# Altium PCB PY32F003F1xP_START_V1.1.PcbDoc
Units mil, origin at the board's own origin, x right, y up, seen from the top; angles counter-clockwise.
Board outline 2126.87 x 1182.75 mil, 2 copper layers (Top Layer, Bottom Layer); 29 components, 28 nets, 127 pads, 22 vias.
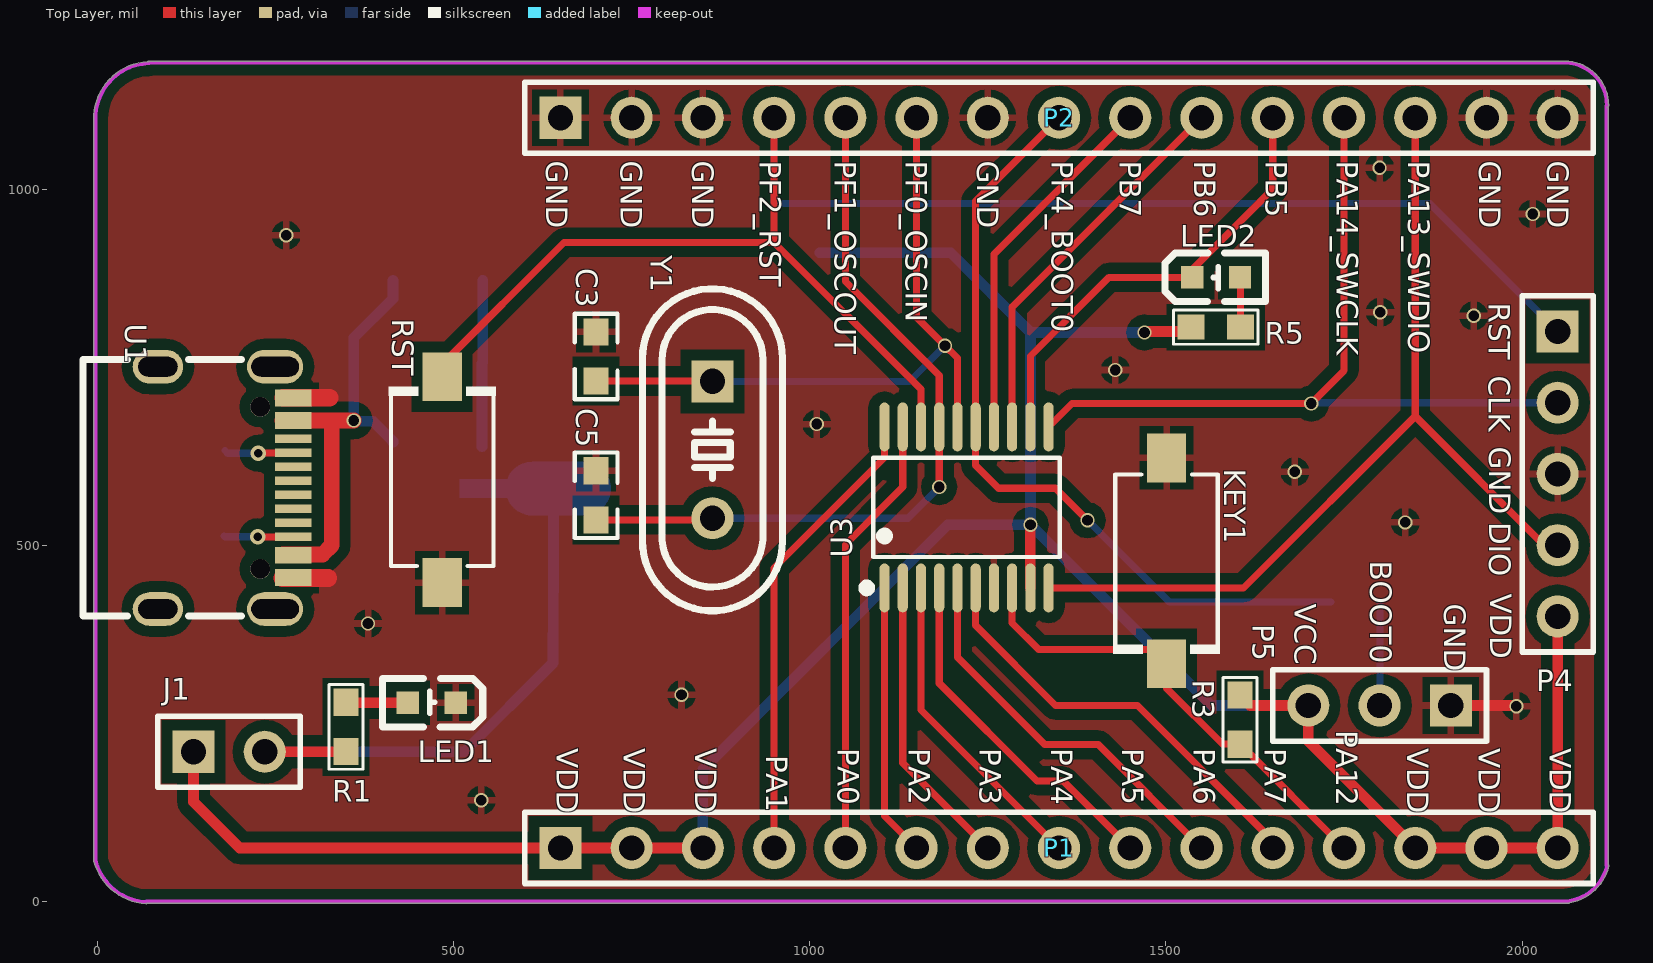
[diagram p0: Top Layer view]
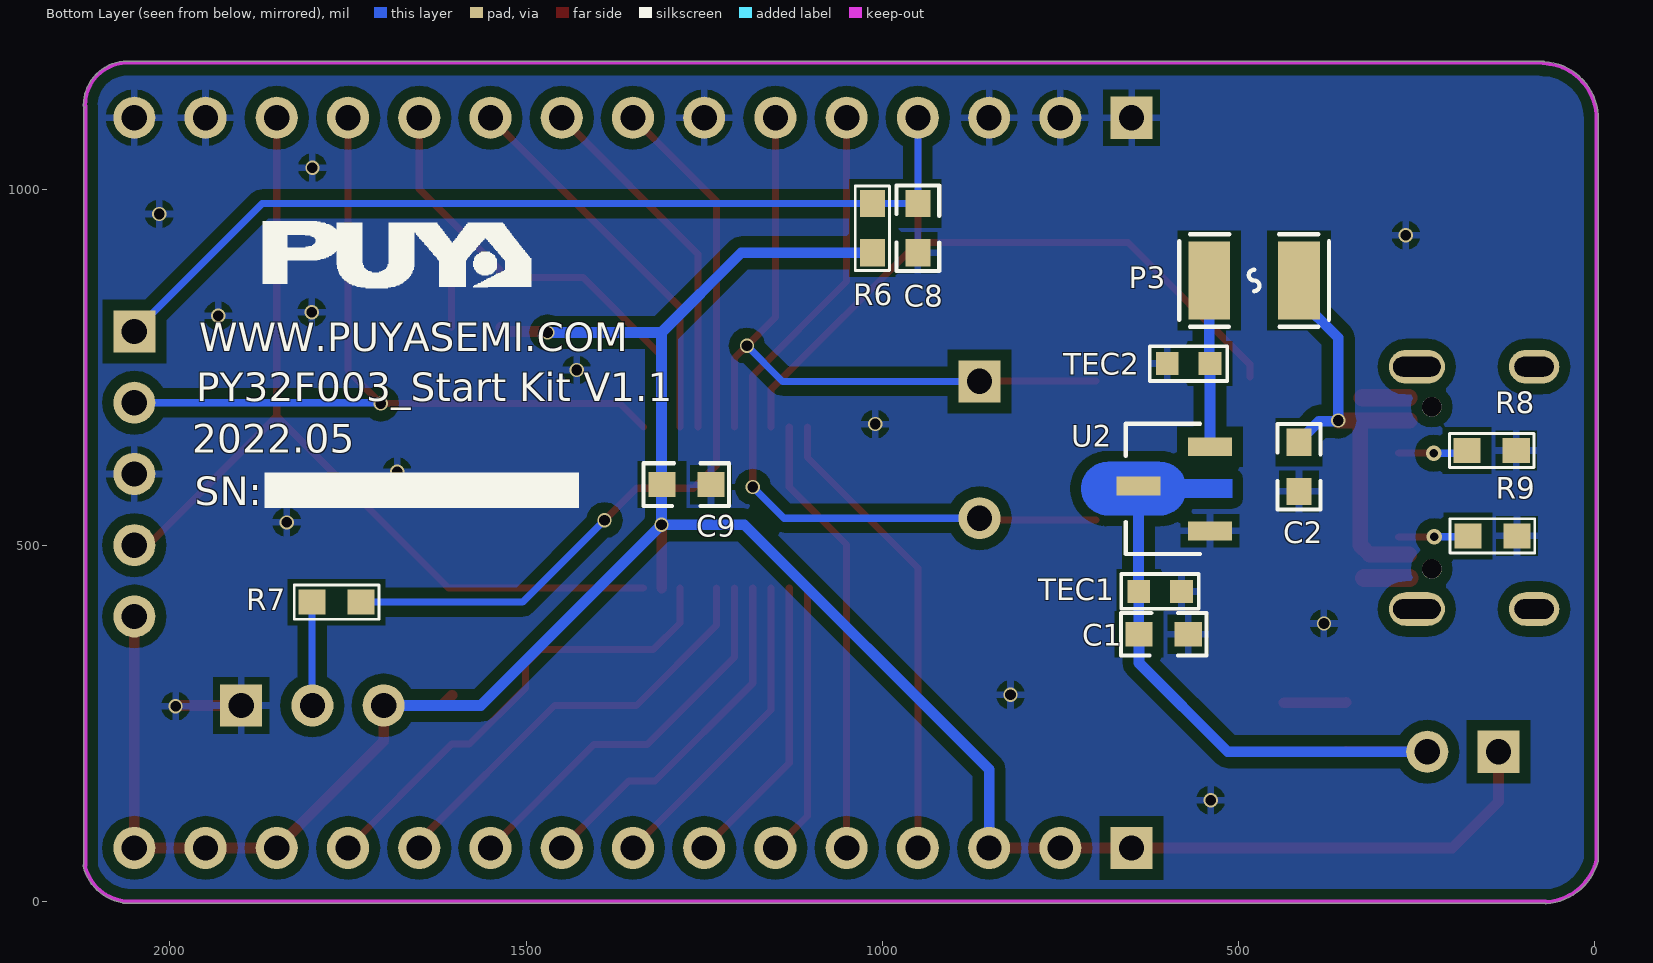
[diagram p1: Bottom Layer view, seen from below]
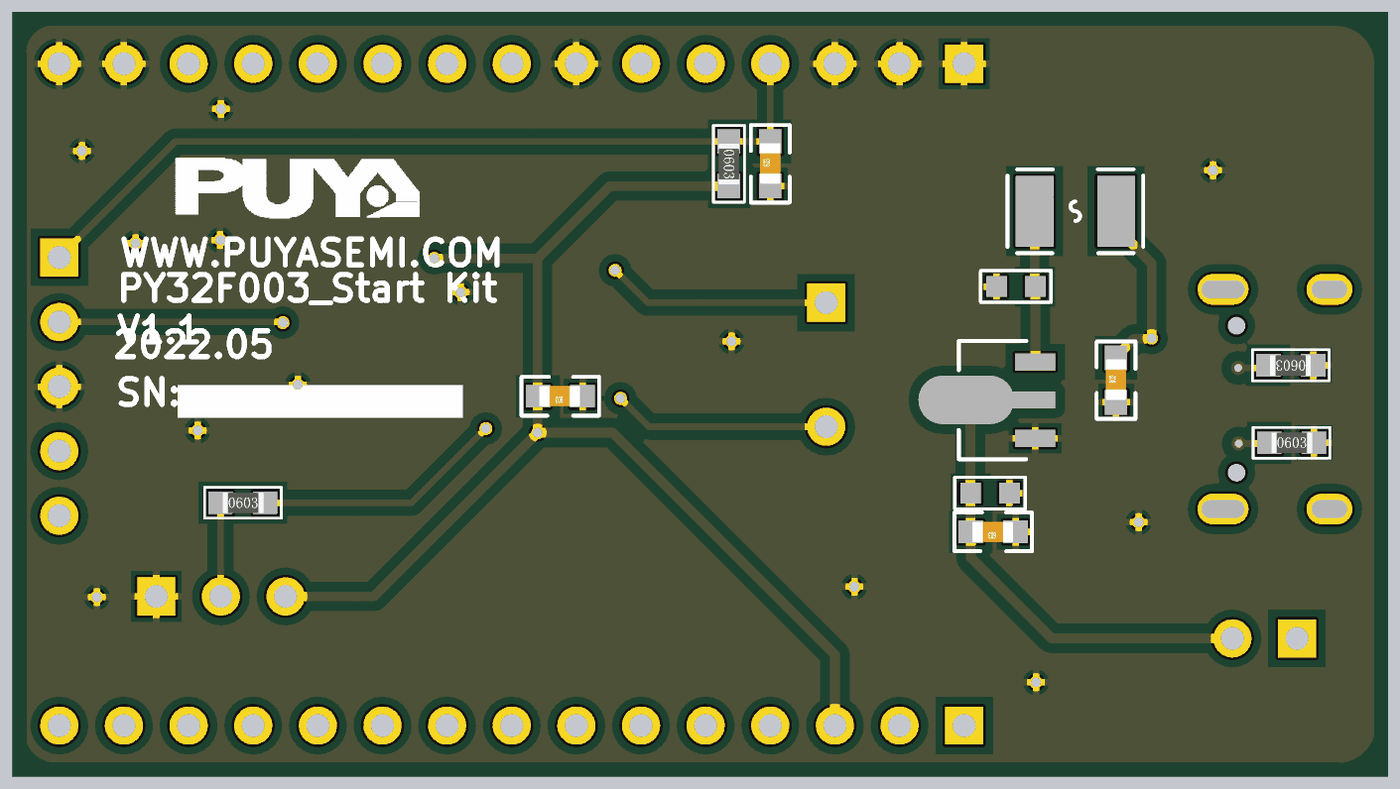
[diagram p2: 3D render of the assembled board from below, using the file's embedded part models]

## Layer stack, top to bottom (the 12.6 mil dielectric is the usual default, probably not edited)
Top Layer: signal copper 1.4
Dielectric: dielectric 12.6, FR-4, Dk 4.8
Bottom Layer: signal copper 1.4

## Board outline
68.32,-3.24 cw(c72.79,76.93) -4.93,56.79 cw(c-2.5,57.42) -5.02,57.42 -5.02,1096.79 cw(c-2.51,1097) -5.02,1096.93 cw(c74.74,1099.04) 70.88,1178.73 cw(c72.7,1177) 72.7,1179.52 2060,1179.52 cw(c2060,1177) 2060.02,1179.52 cw(c2059.5,1117.5) 2121.52,1117.5 cw(c2059.5,1117.5) 2121.51,1116.98 cw(c2119,1117) 2118.86,1114.49 cw(c2118.5,1112) 2121.01,1112 2121.01,51.66 cw(c2119.33,49.8) 2121.84,49.8 cw(c2119.33,49.8) 2121.77,49.2 cw(c2055.5,65.5) 2066.74,-1.81 cw(c2065,0) 2065,-2.51 2061.11,-2.51 cw(c2055.5,65.5) 2049.89,-2.51 70.23,-2.51 cw(c68.46,-0.72)

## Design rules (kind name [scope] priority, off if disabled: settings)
Clearance poly [InPolygon] p1: gap=15
Clearance [All] p2: gap=6
ComponentClearance [All] p1: gap=0 collisioncheckmode=3 verticalgap=0 showdistances=FALSE
HoleToHoleClearance [All] p1: gap=3 allowstackedmicrovias=TRUE
MinimumSolderMaskSliver [All] p1: minsoldermaskwidth=0
NetAntennae [All] p1: netantennaetolerance=6
PolygonConnect [All] p1: connectstyle=Relief reliefconductorwidth=10 reliefentries=4 polygonreliefangle="90 Angle"
RoutingVias [All] p1: holewidth=28 width=50 viastyle="Through Hole" minholewidth=28 minwidth=50 maxholewidth=28 maxwidth=50
SilkToSilkClearance [All] p1: silktosilkclearance=0
SilkscreenOverComponentPads SilkToSolderMaskClearance [IsPad] p1: minsilkscreentomaskgap=0
SolderMaskExpansion [All] p1: expansion=4
Width [All] p1: maxlimit=30 minlimit=10 preferedwidth=10
22 further rules are at their usual default settings.

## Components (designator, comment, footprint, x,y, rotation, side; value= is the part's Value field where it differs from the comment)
C1 "0.1uF/50V" 0603C 605,375 r0 bottom
C2 "0.1uF/50V" 0603C 415,610 r90 bottom
C3 "22pF" 0603C 700,765 r270 top
C5 "22pF" 0603C 700,570 r90 top
C8 "0.1uF/50V" 0603C 950,945 r90 bottom
C9 "0.1uF/50V" 0603C 1275,585 r0 bottom
J1 "JUMP" HDR1X2 135,210 r0 top
KEY1 "1TS002B-2600-5001" SW 1500,525 r270 top (schematic designator SW1)
LED1 "RED" 0603_LED 455,280 r180 top
LED2 "GREEN" 0603_LED 1585,875 r0 top
P1 "Header 15" HDR1X15 650,75 r0 top
P2 "Header 15" HDR1X15 650,1100 r0 top
P3 "SMD1210P005TF" SDM1210P005TF 475,850 r0 bottom
P4 "Debug" HDR1X5 2050,800 r270 top
P5 "Header 3" HDR1X3 1900,275 r180 top
R1 "470Ω" 0603R 350,245 r90 top
R3 "1.5K" 0603R 1605,255 r90 top
R5 "680Ω" 0603R 1570,805 r0 top
R6 "10K" 0603R 1015,945 r270 bottom
R7 "10K" 0603R 1766,419 r180 bottom
R8 "5.1k" 0603R 144.5,634 r0 bottom
R9 "5.1K" 0603R 143.5,512 r180 bottom
RST "1TS002B-2600-5001" SW 485,545 r90 top (schematic designator SW3)
TEC1 "10uF" 0603 610,435 r0 bottom
TEC2 "10uF" 0603 570,755 r180 bottom
U1 "KH-TYPE-C-16P" USB-C-SMD_KH-TYPE-C-16P 135,574 r270 top
U2 "LM1117-3.3" LM1117-3.3 540,520 r180 bottom
U3 "PY32F003" TSSOP20 1105,440 r0 top
Y1 "24M" 25MHZ_2 860,600 r270 top

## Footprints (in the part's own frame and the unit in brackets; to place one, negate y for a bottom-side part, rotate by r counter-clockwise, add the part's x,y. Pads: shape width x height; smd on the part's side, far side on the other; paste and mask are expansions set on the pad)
25MHZ_2 [mm]
  rect 1.5x1.5 hole 0.9: 1(-3.302,0.087)
  round 1.5 hole 0.9: 2(1.578,0.087)
  silkscreen extent -6.6,-2.41 4.88,2.59
0603 [mil]
  rect 32x32 smd: 1(30,0) 2(-30,0)
  silkscreen extent -54,-25 55,24
0603_LED [mil]
  rect 31.5x31.5 smd: 1(19,1) 2(-48,1)
  silkscreen extent -86,-33 55,35
0603C [mil]
  rect 38x35 smd: 1(-34.5,0) 2(34.5,0)
  silkscreen extent -60,-30 60,30, body extent -31,-16 32,16, height 12
0603R [mil]
  rect 38x35 smd: 1(-34.5,1) 2(34.5,1)
  silkscreen extent -59,-23 59,25, body extent -31,-15 32,17, height 18
HDR1X2 [mm] "Connector; Header; 2 Position"
  rect 1.5x1.5 hole 0.9: 1(0,0)
  round 1.5 hole 0.9: 2(2.54,0)
  silkscreen extent -1.27,-1.27 3.81,1.27
HDR1X3 [mm] "Connector; Header; 3 Position"
  rect 1.5x1.5 hole 0.9: 1(0,0)
  round 1.5 hole 0.9: 2(2.54,0) 3(5.08,0)
  silkscreen extent -1.27,-1.27 6.35,1.27
HDR1X5 [mm] "Connector; Header; 5 Position"
  rect 1.5x1.5 hole 0.9: 1(0,0)
  round 1.5 hole 0.9: 2(2.54,0) 3(5.08,0) 4(7.62,0) 5(10.16,0)
  silkscreen extent -1.27,-1.27 11.43,1.27
HDR1X15 [mm]
  rect 1.5x1.5 hole 0.9: 1(0,0)
  round 1.5 hole 0.9: 2(2.54,0) 3(5.08,0) 4(7.62,0) 5(10.16,0) 6(12.7,0) 7(15.24,0) 8(17.78,0) 9(20.32,0) 10(22.86,0) 11(25.4,0) 12(27.94,0) 13(30.48,0) 14(33.02,0) 15(35.56,0)
  silkscreen extent -1.27,-1.27 36.83,1.27
LM1117-3.3 [mm]
  rect 1.575x0.672 smd: 1(0,0) 2(-2.55,1.598) 3(0,3)
  Top Layer region: -3.64,2.459 -1.785,2.459 -1.741,2.458 -1.696,2.455 -1.652,2.449 -1.608,2.442 -1.565,2.433 -1.522,2.421 -1.479,2.408 -1.437,2.393 -1.396,2.375 -1.356,2.356 -1.317,2.335 -1.279,2.312 -1.241,2.288 -1.206,2.261 -1.171,2.233 -1.138,2.204 -1.106,2.173 -1.075,2.14 -1.047,2.106 -1.019,2.071 -0.994,2.034 -0.97,1.996 -0.948,1.958 -0.928,1.918 -0.91,1.839 0.788,1.839 0.788,1.179 -0.91,1.179 -0.928,1.099 -0.948,1.06 -0.97,1.021 -0.994,0.983 -1.019,0.947 -1.047,0.911 -1.075,0.877 -1.106,0.845 -1.138,0.814 -1.171,0.784 -1.206,0.756 -1.241,0.73 -1.279,0.705 -1.317,0.682 -1.356,0.661 -1.396,0.642 -1.437,0.625 -1.479,0.609 -1.522,0.596 -1.565,0.585 -1.608,0.575 -1.652,0.568 -1.696,0.563 -1.741,0.56 -1.785,0.559 -3.64,0.559 -3.684,0.56 -3.728,0.563 -3.773,0.568 -3.817,0.575 -3.86,0.585 -3.903,0.596 -3.946,0.609 -3.988,0.625 -4.029,0.642 -4.069,0.661 -4.108,0.682 -4.146,0.705 -4.183,0.73 -4.219,0.756 -4.254,0.784 -4.287,0.814 -4.319,0.845 -4.349,0.877 -4.378,0.911 -4.405,0.947 -4.431,0.983 -4.455,1.021 -4.477,1.06 -4.497,1.099 -4.515,1.14 -4.531,1.181 -4.546,1.224 -4.558,1.266 -4.568,1.31 -4.577,1.353 -4.583,1.398 -4.587,1.442 -4.589,1.486 -4.589,1.531 -4.587,1.575 -4.583,1.62 -4.577,1.664 -4.568,1.708 -4.558,1.751 -4.546,1.794 -4.531,1.836 -4.515,1.877 -4.497,1.918 -4.477,1.958 -4.455,1.996 -4.431,2.034 -4.405,2.071 -4.378,2.106 -4.349,2.14 -4.319,2.173 -4.287,2.204 -4.254,2.233 -4.219,2.261 -4.183,2.288 -4.146,2.312 -4.108,2.335 -4.069,2.356 -4.029,2.375 -3.988,2.393 -3.946,2.408 -3.903,2.421 -3.86,2.433 -3.817,2.442 -3.773,2.449 -3.728,2.455 -3.684,2.458
  silkscreen extent -3.01,-0.83 -0.35,3.83
SDM1210P005TF [mm]
  rect 1.485x2.781 smd: 1(-1.524,-0.549) 2(1.676,-0.549)
  silkscreen extent -2.59,-2.2 2.74,1.1
SW [mm]
  rect 1.74x1.4 smd: 1(-2.476,0.024) 2(4.864,0.024)
  silkscreen extent -1.88,-1.88 4.5,1.93
TSSOP20 [mm]
  oval 0.364x1.742 smd: 1(0,0) 2(0.65,0) 3(1.3,0) 4(1.95,0) 5(2.6,0) 6(3.25,0) 7(3.9,0) 8(4.55,0) 9(5.2,0) 10(5.85,0) 11(5.85,5.742) 12(5.2,5.742) 13(4.55,5.742) 14(3.9,5.742) 15(3.25,5.742) 16(2.6,5.742) 17(1.95,5.742) 18(1.3,5.742) 19(0.65,5.742) 20(0,5.742)
  silkscreen extent -0.78,-0.15 6.25,4.64
USB-C-SMD_KH-TYPE-C-16P [mm] "https://item.szlcsc.com/747093.html"
  oval 1.2x2 hole 0.7 slot 1.7 at 90 deg: 1(-4.484,2.908) 2(4.156,2.908)
  oval 1.2x1.8 hole 0.7 slot 1.4 at 90 deg: 3(-4.484,-1.272) 4(4.156,-1.272)
  rect 0.3x1.3 smd: A1(-3.514,3.558) A4(-2.714,3.558) A5(-1.414,3.558) A6(-0.414,3.558) A7(0.086,3.558) A8(1.086,3.558) A9(2.386,3.558) A12(3.186,3.558) B1(2.886,3.558) B4(2.086,3.558) B5(1.586,3.558) B6(0.586,3.558) B7(-0.914,3.558) B8(-1.914,3.558) B9(-2.414,3.558) B12(-3.214,3.558)
  round 0.7 hole 0.7 unplated: ""(-3.054,2.378) ""(2.726,2.378)
  silkscreen extent -4.74,-3.94 4.41,1.72

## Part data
C1 C3 C5: library part Cap, "Capacitor"
C2 C8 C9: library part CAP, "Capacitor"
LED1 LED2: library part PDI-E803_Dup1
P1 P2: "Header, 15-Pin"
P4: library part CON5
P5: "Header, 3-Pin"
R1 R3 R5 R6 R7: library part Res, "Resistor"
R8 R9: library part Res_1, "Resistor"
TEC1 TEC2: library part 贴片钽电容
U3: library part Component_1
Y1: library part CRYSTAL, "Crystal"

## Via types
v1: diameter 20, hole 15, Top Layer to Bottom Layer, 20 vias
v2: diameter 22, hole 12, Top Layer to Bottom Layer, tented both sides, 2 vias

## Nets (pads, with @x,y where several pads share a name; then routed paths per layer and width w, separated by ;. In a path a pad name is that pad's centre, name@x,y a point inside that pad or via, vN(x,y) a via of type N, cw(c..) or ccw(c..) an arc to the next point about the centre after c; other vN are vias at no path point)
Boot0: P2.8 R7.2 U3.15 | length 1114.5
  Top Layer w10: P2.8 1232.95,982.95 U3.15 1232.95,612.05 1265,580 1345,580 v1(1390,535)
  Bottom Layer w10: v1(1390,535) 1505,420 R7.2
GND: C1.1 C2.1 C3.1 C5.2 C8.1 C9.1 KEY1.1 LED1.2 P2.1 P2.2 P2.3 P2.7 P2.14 P2.15 P4.3 P5.1 R8.1 R9.2 RST.1 TEC1.2 TEC2.2 U1.A1 U1.A12 U1.B1 U1.B12 U2.1 U3.7 | length 221.4
  Top Layer w15: P5.1 1991,275 v1(1992,274)
  Top Layer w25: U1.A12@260,454 324,454 ; U1.A1@261,707 326,707
  other v1: 539,142 820,290 380,390 1836,532 1681,603 1010,670 1429,746 1932,822 1801,827 265,935 2015,965 1800,1030
MCU_RST: C8.2 P2.4 P4.1 R6.1 RST.2 U3.18 | length 2368.5
  Top Layer w10: RST.2 484.04,754.04 655,925 950,925 ; P2.4 950,925 ; U3.18 1156.18,718.82 950,925
  Bottom Layer w10: P2.4 C8.2 R6.1 1870.5,979.5 P4.1
MCU_VDD: C9.2 J1.1 P1.1 P1.2 P1.3 P1.13 P1.14 P1.15 P4.5 P5.3 R3.2 R5.1 R6.2 U3.9 | length 3839.8
  Top Layer w15: J1.1 135,140 200,75 P1.1 P1.2 P1.3 ; U3.9 v1@1309.72,530 ; v1(1469.96,798.59) 1471.37,800 1529.5,800 R5.1 ; R3.2 1618.5,275 P5.3 1700,225 P1.13 P1.14 P1.15 P4.5
  Bottom Layer w15: P1.3 850,185 1193.59,528.59 v1(1309.96,528.59) ; R6.2 1198.13,910.5 1310.04,798.59 ; C9.2 1310.04,585.54 1310.04,798.59 ; C9.2 1310,584.54 v1(1309.96,528.59) v1(1309.96,528.59) ; v1(1469.96,798.59) 1310.04,798.59 ; P5.3 1563.54,275 v1(1309.96,528.59)
NetC1_2: C1.2 J1.2 R1.1 TEC1.1 U2.2 | length 819
  Top Layer w15: J1.2 348.5,210 R1.1
  Bottom Layer w15: J1.2 515,210 639.5,334.5 C1.2 640,375.5 TEC1.1 640.38,435.38 U2.2
NetLED1_1: LED1.1 R1.2 | length 87.2
  Top Layer w15: R1.2 349.5,279 LED1.1
NetLED2_1: LED2.1 R5.2 | length 69.5
  Top Layer w10: R5.2 LED2.1@1604.5,875.5
NetP3_2: P3.2 TEC2.1 U2.3 | length 233.9
  Bottom Layer w15: U2.3 TEC2.1 540.98,755.98 P3.2
NetP5_2: P5.2 R7.1 | length 145.2
  Bottom Layer w10: P5.2 1800.5,275.5 R7.1
NetR8_2: R8.2 U1.A5 | length 98
  Top Layer w10: v2(226,629) 226.67,629.67 U1.A5
  Bottom Layer w10: R8.2 183,629 v2(226,629)
NetR9_1: R9.1 U1.B5 | length 98
  Top Layer w10: v2@225,512 225.44,511.56 U1.B5
  Bottom Layer w10: R9.1 179.22,511.78 v2(225.22,511.78)
OSCIN: C3.2 P2.6 U3.16 Y1.1 | length 968.6
  Top Layer w10: C3.2 862.91,730.5 Y1.1 ; P2.6 1150,820 v1(1190,780) 1207.36,762.64 U3.16
  Bottom Layer w10: Y1.1 1139.99,729.99 v1(1190,780)
OSCOUT: C5.1 P2.5 U3.17 Y1.2 | length 1073.7
  Top Layer w10: C5.1 861.06,535.5 Y1.2 ; P2.5 1050,870 1181.77,738.23 U3.17 v1(1181.77,581.77)
  Bottom Layer w10: Y1.2 1137.86,537.86 v1(1181.77,581.77)
PA0: P1.5 U3.19 | length 624.4
  Top Layer w10: P1.5 1050,501 1130.59,581.59 U3.19
PA1: P1.4 U3.20 | length 655.3
  Top Layer w10: P1.4 950,468 1105,623 U3.20
PA2: P1.6 U3.1 | length 383.6
  Top Layer w10: U3.1 1105,120 P1.6
PA3: P1.7 U3.2 | length 414.5
  Top Layer w10: U3.2 1130.59,194.41 P1.7
PA4: P1.8 U3.3 | length 445.3
  Top Layer w10: U3.3 1156.18,268.82 P1.8
PA5: P1.9 U3.4 | length 497.8
  Top Layer w10: U3.4 1181.77,306.23 1319,169 1356,169 P1.9
PA6: P1.10 U3.5 | length 550.9
  Top Layer w10: U3.5 1207.36,342.64 1330,220 1405,220 P1.10
PA7: P1.11 U3.6 | length 605.1
  Top Layer w10: U3.6 1232.95,387.05 1345,275 1460,275 1650,85 P1.11
PA12: KEY1.2 P1.12 R3.1 U3.8 | length 666
  Top Layer w10: U3.8 1284.13,390.87 1321.5,353.5 1480.96,353.5 KEY1.2 1500.96,299.04 1579.25,220.75 1604.25,220.75 P1.12
PB5: LED2.2 P2.11 U3.12 | length 643.4
  Top Layer w10: U3.12 1309.72,765.72 1420,876 LED2.2 1537,887 1650,1000 P2.11
PB6: P2.10 U3.13 | length 544.1
  Top Layer w10: U3.13 1284.13,834.13 P2.10
PB7: P2.9 U3.14 | length 513.2
  Top Layer w10: U3.14 1258.54,908.54 P2.9
SWCLK: P2.12 P4.2 U3.11 | length 1150.4
  Top Layer w10: U3.11 1368.25,699 v1(1704,699) ; v1@1706,699 v1(1704,699) ; P2.12 1750,745 v1(1704,699)
  Bottom Layer w10: v1@1704,700 P4.2
SWDIO: P2.13 P4.4 U3.10 | length 1308.5
  Top Layer w10: U3.10 1609,440 1850,681 ; P2.13 1850,681 ; P4.4 2031,500 1850,681
Type_C: C2.2 P3.1 U1.A4 U1.A9 U1.B4 U1.B9 | length 637.7
  Top Layer w22: U1.A4@259.66,675 329,675 ; U1.B4@260,487 316.11,487 329,499.89 329,675 ; v1(360,675) 329,675
  Bottom Layer w15: C2.2 415,646 386.96,674.04 360.96,674.04 v1(360,675) 360,791.09 415,846.09 P3.1
pads on no net: U1. U1.1 U1.2 U1.3 U1.4 U1.A6 U1.A7 U1.A8 U1.B6 U1.B7 U1.B8

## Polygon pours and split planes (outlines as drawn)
GND on Bottom Layer "Top-GND" (solid, remove dead copper, pour order 13): -4,1177 2118,1177 2118,1 -1,1
GND on Top Layer "Top-GND" (solid, remove dead copper, pour order 15): -1,1 2118,1 2118,1177 -3,1177

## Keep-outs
Keep-Out Layer:
  lines w5: -2.51,1097 cw(c74.74,1099.04) 72.7,1176.28 ; -2.5,1098 -2.5,57.42 ccw(c72.79,76.93) 68.46,-0.72 ; 68.5,0 2065,0 ; 72.7,1177 262.5,1177 2059.5,1177 ; 2050,0 ccw(c2055.5,65.5) 2119.33,49.8 ; 2060,1177 cw(c2059.5,1117.5) 2119,1117 ; 2118.5,50 2118.5,1117

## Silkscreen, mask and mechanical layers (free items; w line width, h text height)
Top Overlay:
  text "GND" at 630,1040 h30 r270
  text "GND" at 735,1040 h30 r270
  text "GND" at 835,1040 h30 r270
  text "PF2_RST" at 930,1040 h30 r270
  text "PF1_OSCOUT" at 1035,1040 h30 r270
  text "PF0_OSCIN" at 1135,1040 h30 r270
  text "GND" at 1235,1040 h30 r270
  text "PF4_BOOT0" at 1340,1040 h30 r270
  text "PB7" at 1435,1040 h30 r270
  text "PB6" at 1540,1040 h30 r270
  text "PB5" at 1640,1040 h30 r270
  text "PA14_SWCLK" at 1740,1040 h30 r270
  text "PA13_SWDIO" at 1840,1040 h30 r270
  text "GND" at 1940,1040 h30 r270
  text "GND" at 2035,1040 h30 r270
  text "RST" at 1953,840 h30 r270
  text "CLK" at 1953,738 h30 r270
  text "GND" at 1954,638 h30 r270
  text "DIO" at 1954,532 h30 r270
  text "BOOT0" at 1787,478.02 h30 r270
  text "VDD" at 1955,432 h30 r270
  text "VCC" at 1681,418.04 h30 r270
  text "GND" at 1891,418.04 h30 r270
  text "PA12" at 1739,239.99 h30 r270
  text "VDD" at 645,215 h30 r270
  text "VDD" at 739,215 h30 r270
  text "VDD" at 839,215 h30 r270
  text "PA0" at 1039,215 h30 r270
  text "PA2" at 1139,215 h30 r270
  text "PA3" at 1239,215 h30 r270
  text "PA4" at 1339,215 h30 r270
  text "PA5" at 1439,215 h30 r270
  text "PA6" at 1539,215 h30 r270
  text "PA7" at 1639,215 h30 r270
  text "VDD" at 1839,215 h30 r270
  text "VDD" at 1939,215 h30 r270
  text "VDD" at 2039,215 h30 r270
  text "PA1" at 939,205 h30 r270
Bottom Overlay:
  drawing of 448 lines, arcs and shapes, not listed
  text "WWW.PUYASEMI.COM" at 1959,772 h40
  text "PY32F003_Start Kit V1.1" at 1963,702 h40
  text "2022.05" at 1969,630 h40
  text "SN:" at 1965,556 h40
